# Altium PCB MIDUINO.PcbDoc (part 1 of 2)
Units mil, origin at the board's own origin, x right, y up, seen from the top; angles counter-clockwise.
Board outline 26720 x 2625 mil, 2 copper layers (Top Layer, Bottom Layer); 230 components, 129 nets, 640 pads, 170 vias.
Unrouted connection lines stored in the file: 1.
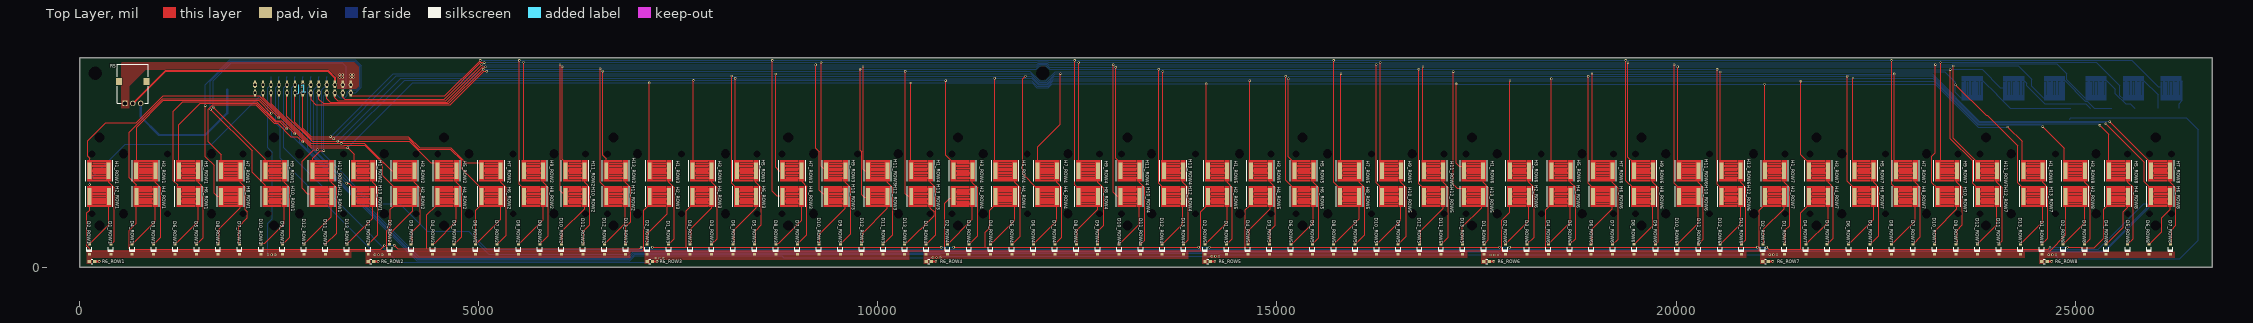
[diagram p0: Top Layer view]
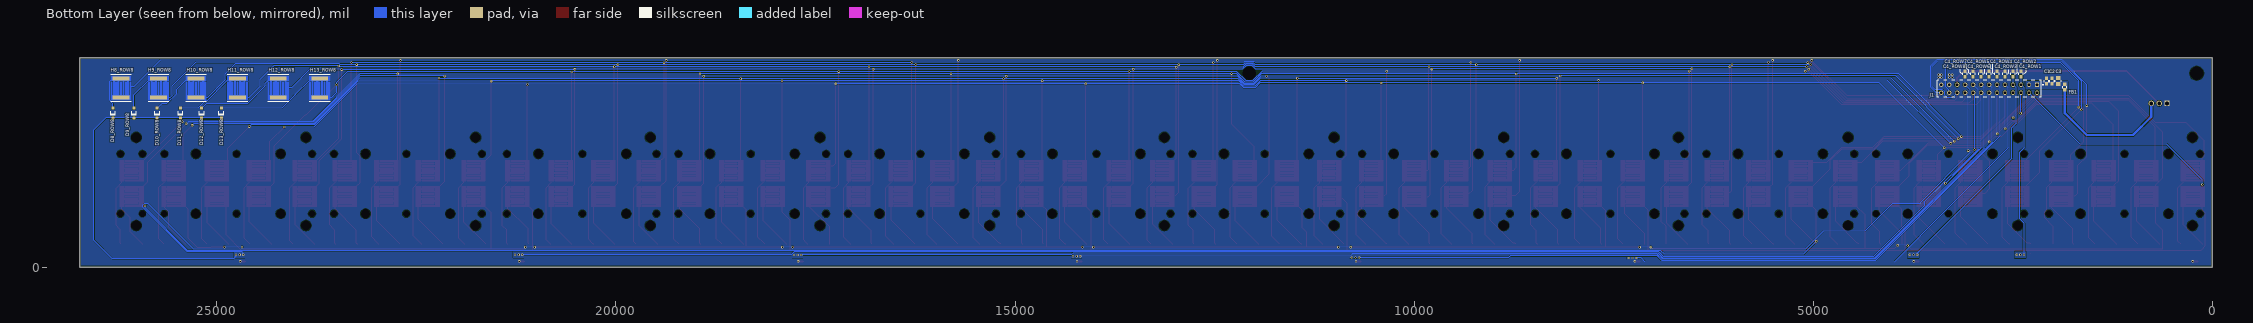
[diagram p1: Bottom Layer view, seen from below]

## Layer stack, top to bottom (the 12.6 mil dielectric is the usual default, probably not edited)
Top Solder: solder mask 0.4, Solder Resist, Dk 3.5
Top Layer: signal copper 1.4
Dielectric 1: dielectric 12.6, FR-4, Dk 4.8
Bottom Layer: signal copper 1.4
Bottom Solder: solder mask 0.4, Solder Resist, Dk 3.5

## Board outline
0,0 0,2625 26720,2625 26720,0

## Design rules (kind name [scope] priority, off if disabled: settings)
AcuteAngle [All] p1: minimum=6.00000000000000E+0001 checktracksonly=FALSE
BoardOutlineClearance [All] p1: gap=20 ignorepadtopadclearanceinfootprint=FALSE
Clearance Clearance_1 [InNamedPolygon('GPS_GND') vs HasFootprint('0603CS')] p1: gap=10 ignorepadtopadclearanceinfootprint=FALSE
Clearance [All] p2: gap=6 ignorepadtopadclearanceinfootprint=FALSE except(0: Arc-Hole Track-Hole SMDPad-Hole THPad-Hole Via-Hole Fill-Hole Poly-Hole Region-Hole Text-Hole; 8: Arc-Poly Track-Poly SMDPad-Poly THPad-Poly Via-Poly Fill-Poly Poly-Poly Poly-Region Poly-Text)
ComponentClearance ComponentClearance_TestPad [HasFootprint('TEST-SMT')] p1: gap=5 collisioncheckmode=3 verticalgap=10 showdistances=FALSE
ComponentClearance [All] p2: gap=10 collisioncheckmode=3 verticalgap=10 showdistances=FALSE
DiffPairsRouting DiffPairsRoutingDBGUSB [InDifferentialPair('USB_DBG')] p1: maxlimit=60 minlimit=10 mostfreqgap=10 toplayer_minwidth=6 toplayer_maxwidth=30 toplayer_prefwidth=10 bottomlayer_minwidth=6 bottomlayer_maxwidth=30 bottomlayer_prefwidth=10 maxuncoupledlength=500
DiffPairsRouting DiffPairsRouting_USBDBG [InDifferentialPair('USB_DBG')] p2: maxlimit=60 minlimit=10 mostfreqgap=10 toplayer_minwidth=6 toplayer_maxwidth=30 toplayer_prefwidth=10 bottomlayer_minwidth=6 bottomlayer_maxwidth=30 bottomlayer_prefwidth=10 maxuncoupledlength=500
DiffPairsRouting DiffPairsRoutingUSB [InDifferentialPair('USB')] p3: maxlimit=60 minlimit=10 mostfreqgap=10 toplayer_minwidth=6 toplayer_maxwidth=30 toplayer_prefwidth=10 bottomlayer_minwidth=6 bottomlayer_maxwidth=30 bottomlayer_prefwidth=10 maxuncoupledlength=500
DiffPairsRouting DP_CAN [InNetClass('CAN')] p4: maxlimit=60 minlimit=10 mostfreqgap=10 toplayer_minwidth=6 toplayer_maxwidth=30 toplayer_prefwidth=6 bottomlayer_minwidth=6 bottomlayer_maxwidth=30 bottomlayer_prefwidth=6 maxuncoupledlength=500 // 120ohm zdiff
DiffPairsRouting DP_USB [InDifferentialPair('USB')] p5: maxlimit=60 minlimit=10 mostfreqgap=10 toplayer_minwidth=6 toplayer_maxwidth=30 toplayer_prefwidth=10 bottomlayer_minwidth=6 bottomlayer_maxwidth=30 bottomlayer_prefwidth=10 maxuncoupledlength=500 // 120ohm zdiff
DiffPairsRouting DP_CURR [InNetClass('CURR')] p6: maxlimit=60 minlimit=10 mostfreqgap=10 toplayer_minwidth=6 toplayer_maxwidth=12 toplayer_prefwidth=6 bottomlayer_minwidth=6 bottomlayer_maxwidth=12 bottomlayer_prefwidth=6 maxuncoupledlength=500 // 120ohm zdiff
DiffPairsRouting [InDifferentialPairClass('All Differential Pairs')] p7: maxlimit=60 minlimit=12 mostfreqgap=12 toplayer_minwidth=6 toplayer_maxwidth=12 toplayer_prefwidth=8 bottomlayer_minwidth=6 bottomlayer_maxwidth=12 bottomlayer_prefwidth=8 maxuncoupledlength=500
Height [All] p1: minheight=0 maxheight=2000 prefheight=500
HoleSize [All] p1: absolutevalues=TRUE maxlimit=250 minlimit=15 maxpercent=80.000 minpercent=20.000
HoleToHoleClearance [All] p1: gap=15 allowstackedmicrovias=FALSE
MinimumAnnularRing [All] p1: minimumring=6
MinimumSolderMaskSliver [All] p1: minsoldermaskwidth=0
PasteMaskExpansion [All] p1: expansion=1
PlaneClearance [All] p1: clearance=10
PlaneConnect [All] p1: planeconnectstyle=Direct reliefexpansion=10 reliefentries=4 reliefconductorwidth=10 reliefairgap=7
PolygonConnect [All] p1: connectstyle=Direct reliefconductorwidth=10 reliefentries=4 polygonreliefangle="90 Angle" airgapwidth=10
RoutingVias [All] p1: holewidth=15 width=30 viastyle="Through Hole" minholewidth=15 minwidth=27 maxholewidth=30 maxwidth=100
SilkToSilkClearance [All] p1: silktosilkclearance=1
SilkToSolderMaskClearance [IsPad] p1: minsilkscreentomaskgap=1 clearancetoexposedcopper=TRUE
SolderMaskExpansion ViaTent [isVia] p1: expansion=-100 istentingtop=FALSE
SolderMaskExpansion ViaTenting [isVia] p2: expansion=-20 istentingtop=FALSE
SolderMaskExpansion [All] p3: expansion=2.5 istentingtop=FALSE
Width [All] p1: maxlimit=250 minlimit=6 preferedwidth=8
19 further rules are at their usual default settings.

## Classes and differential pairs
channel class Row: ROW1 ROW2 ROW3 ROW4 ROW5 ROW6 ROW7 ROW8
component class ROW8: C4_ROW8 D1_ROW8 D2_ROW8 D3_ROW8 D4_ROW8 D5_ROW8 D6_ROW8 D7_ROW8 D8_ROW8 D9_ROW8 D10_ROW8 D11_ROW8 D12_ROW8 D13_ROW8 H1_ROW8 H2_ROW8 H3_ROW8 H4_ROW8 H5_ROW8 H6_ROW8 H7_ROW8 H8_ROW8 H9_ROW8 H10_ROW8 H11_ROW8 H12_ROW8 H13_ROW8 R6_ROW8
component class ROW7: C4_ROW7 D1_ROW7 D2_ROW7 D3_ROW7 D4_ROW7 D5_ROW7 D6_ROW7 D7_ROW7 D8_ROW7 D9_ROW7 D10_ROW7 D11_ROW7 D12_ROW7 D13_ROW7 H1_ROW7 H2_ROW7 H3_ROW7 H4_ROW7 H5_ROW7 H6_ROW7 H7_ROW7 H8_ROW7 H9_ROW7 H10_ROW7 H11_ROW7 H12_ROW7 H13_ROW7 R6_ROW7
component class ROW6: C4_ROW6 D1_ROW6 D2_ROW6 D3_ROW6 D4_ROW6 D5_ROW6 D6_ROW6 D7_ROW6 D8_ROW6 D9_ROW6 D10_ROW6 D11_ROW6 D12_ROW6 D13_ROW6 H1_ROW6 H2_ROW6 H3_ROW6 H4_ROW6 H5_ROW6 H6_ROW6 H7_ROW6 H8_ROW6 H9_ROW6 H10_ROW6 H11_ROW6 H12_ROW6 H13_ROW6 R6_ROW6
component class ROW5: C4_ROW5 D1_ROW5 D2_ROW5 D3_ROW5 D4_ROW5 D5_ROW5 D6_ROW5 D7_ROW5 D8_ROW5 D9_ROW5 D10_ROW5 D11_ROW5 D12_ROW5 D13_ROW5 H1_ROW5 H2_ROW5 H3_ROW5 H4_ROW5 H5_ROW5 H6_ROW5 H7_ROW5 H8_ROW5 H9_ROW5 H10_ROW5 H11_ROW5 H12_ROW5 H13_ROW5 R6_ROW5
component class ROW4: C4_ROW4 D1_ROW4 D2_ROW4 D3_ROW4 D4_ROW4 D5_ROW4 D6_ROW4 D7_ROW4 D8_ROW4 D9_ROW4 D10_ROW4 D11_ROW4 D12_ROW4 D13_ROW4 H1_ROW4 H2_ROW4 H3_ROW4 H4_ROW4 H5_ROW4 H6_ROW4 H7_ROW4 H8_ROW4 H9_ROW4 H10_ROW4 H11_ROW4 H12_ROW4 H13_ROW4 R6_ROW4
component class ROW3: C4_ROW3 D1_ROW3 D2_ROW3 D3_ROW3 D4_ROW3 D5_ROW3 D6_ROW3 D7_ROW3 D8_ROW3 D9_ROW3 D10_ROW3 D11_ROW3 D12_ROW3 D13_ROW3 H1_ROW3 H2_ROW3 H3_ROW3 H4_ROW3 H5_ROW3 H6_ROW3 H7_ROW3 H8_ROW3 H9_ROW3 H10_ROW3 H11_ROW3 H12_ROW3 H13_ROW3 R6_ROW3
component class ROW2: C4_ROW2 D1_ROW2 D2_ROW2 D3_ROW2 D4_ROW2 D5_ROW2 D6_ROW2 D7_ROW2 D8_ROW2 D9_ROW2 D10_ROW2 D11_ROW2 D12_ROW2 D13_ROW2 H1_ROW2 H2_ROW2 H3_ROW2 H4_ROW2 H5_ROW2 H6_ROW2 H7_ROW2 H8_ROW2 H9_ROW2 H10_ROW2 H11_ROW2 H12_ROW2 H13_ROW2 R6_ROW2
net class ROW[1..8]: ROW1 ROW2 ROW3 ROW4 ROW5 ROW6 ROW7 ROW8
net class COL[1..13]: COL1 COL2 COL3 COL4 COL5 COL6 COL7 COL8 COL9 COL10 COL11 COL12 COL13
component class ROW1: C4_ROW1 D1_ROW1 D2_ROW1 D3_ROW1 D4_ROW1 D5_ROW1 D6_ROW1 D7_ROW1 D8_ROW1 D9_ROW1 D10_ROW1 D11_ROW1 D12_ROW1 D13_ROW1 H1_ROW1 H2_ROW1 H3_ROW1 H4_ROW1 H5_ROW1 H6_ROW1 H7_ROW1 H8_ROW1 H9_ROW1 H10_ROW1 H11_ROW1 H12_ROW1 H13_ROW1 R6_ROW1
component class MIDUINO: C1 C2 C3 FB1 R5 R15

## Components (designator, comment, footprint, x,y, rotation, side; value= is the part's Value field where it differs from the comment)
C1 "CAP 0603 0.01UF 25V 10% X7R" 0603_CAP 2080,2330 r270 bottom value=10nF
C2 "CAP 0603 0.1UF 25V 10% X7R" 0603_CAP 2010,2330 r90 bottom value=100nF
C3 "CAP 0805 10UF 16V 20% X7R" 0805_CAP_60H 1930,2331.34 r270 bottom value=10µF
C4_ROW1 "CAP 0603 0.1UF 25V 10% X7R" 0603_CAP 2400,2420 r270 bottom value=100nF (schematic designator C4)
C4_ROW2 "CAP 0603 0.1UF 25V 10% X7R" 0603_CAP 2500,2420 r270 bottom value=100nF (schematic designator C4)
C4_ROW3 "CAP 0603 0.1UF 25V 10% X7R" 0603_CAP 2600,2420 r270 bottom value=100nF (schematic designator C4)
C4_ROW4 "CAP 0603 0.1UF 25V 10% X7R" 0603_CAP 2700,2420 r270 bottom value=100nF (schematic designator C4)
C4_ROW5 "CAP 0603 0.1UF 25V 10% X7R" 0603_CAP 2800,2420 r270 bottom value=100nF (schematic designator C4)
C4_ROW6 "CAP 0603 0.1UF 25V 10% X7R" 0603_CAP 2900,2420 r270 bottom value=100nF (schematic designator C4)
C4_ROW7 "CAP 0603 0.1UF 25V 10% X7R" 0603_CAP 3000,2420 r270 bottom value=100nF (schematic designator C4)
C4_ROW8 "CAP 0603 0.1UF 25V 10% X7R" 0603_CAP 3100,2420 r270 bottom value=100nF (schematic designator C4)
D1_ROW1 "1N4148W-7-F" DIOD-SOD123-2_V 390.79,224 r270 top (schematic designator D1)
D1_ROW2 "1N4148W-7-F" DIOD-SOD123-2_V 3616.32,224 r270 top (schematic designator D1)
D1_ROW3 "1N4148W-7-F" DIOD-SOD123-2_V 7379.43,224 r270 top (schematic designator D1)
D1_ROW4 "1N4148W-7-F" DIOD-SOD123-2_V 10604.96,224 r270 top (schematic designator D1)
D1_ROW5 "1N4148W-7-F" DIOD-SOD123-2_V 14368.07,224 r270 top (schematic designator D1)
D1_ROW6 "1N4148W-7-F" DIOD-SOD123-2_V 17593.6,224 r270 top (schematic designator D1)
D1_ROW7 "1N4148W-7-F" DIOD-SOD123-2_V 21356.71,224 r270 top (schematic designator D1)
D1_ROW8 "1N4148W-7-F" DIOD-SOD123-2_V 24582.24,224 r270 top (schematic designator D1)
D2_ROW1 "1N4148W-7-F" DIOD-SOD123-2_V 122,224 r270 top (schematic designator D2)
D2_ROW2 "1N4148W-7-F" DIOD-SOD123-2_V 3885.11,224 r270 top (schematic designator D2)
D2_ROW3 "1N4148W-7-F" DIOD-SOD123-2_V 7110.64,224 r270 top (schematic designator D2)
D2_ROW4 "1N4148W-7-F" DIOD-SOD123-2_V 10873.75,224 r270 top (schematic designator D2)
D2_ROW5 "1N4148W-7-F" DIOD-SOD123-2_V 14099.28,224 r270 top (schematic designator D2)
D2_ROW6 "1N4148W-7-F" DIOD-SOD123-2_V 17862.39,224 r270 top (schematic designator D2)
D2_ROW7 "1N4148W-7-F" DIOD-SOD123-2_V 21087.92,224 r270 top (schematic designator D2)
D2_ROW8 "1N4148W-7-F" DIOD-SOD123-2_V 24851.03,224 r270 top (schematic designator D2)
D3_ROW1 "1N4148W-7-F" DIOD-SOD123-2_V 928.38,224 r270 top (schematic designator D3)
D3_ROW2 "1N4148W-7-F" DIOD-SOD123-2_V 4153.91,224 r270 top (schematic designator D3)
D3_ROW3 "1N4148W-7-F" DIOD-SOD123-2_V 7917.02,224 r270 top (schematic designator D3)
D3_ROW4 "1N4148W-7-F" DIOD-SOD123-2_V 11142.55,224 r270 top (schematic designator D3)
D3_ROW5 "1N4148W-7-F" DIOD-SOD123-2_V 14905.66,224 r270 top (schematic designator D3)
D3_ROW6 "1N4148W-7-F" DIOD-SOD123-2_V 18131.18,224 r270 top (schematic designator D3)
D3_ROW7 "1N4148W-7-F" DIOD-SOD123-2_V 21894.3,224 r270 top (schematic designator D3)
D3_ROW8 "1N4148W-7-F" DIOD-SOD123-2_V 25119.82,224 r270 top (schematic designator D3)
D4_ROW1 "1N4148W-7-F" DIOD-SOD123-2_V 659.59,224 r270 top (schematic designator D4)
D4_ROW2 "1N4148W-7-F" DIOD-SOD123-2_V 4422.7,224 r270 top (schematic designator D4)
D4_ROW3 "1N4148W-7-F" DIOD-SOD123-2_V 7648.23,224 r270 top (schematic designator D4)
D4_ROW4 "1N4148W-7-F" DIOD-SOD123-2_V 11411.34,224 r270 top (schematic designator D4)
D4_ROW5 "1N4148W-7-F" DIOD-SOD123-2_V 14636.87,224 r270 top (schematic designator D4)
D4_ROW6 "1N4148W-7-F" DIOD-SOD123-2_V 18399.98,224 r270 top (schematic designator D4)
D4_ROW7 "1N4148W-7-F" DIOD-SOD123-2_V 21625.5,224 r270 top (schematic designator D4)
D4_ROW8 "1N4148W-7-F" DIOD-SOD123-2_V 25388.62,224 r270 top (schematic designator D4)
D5_ROW1 "1N4148W-7-F" DIOD-SOD123-2_V 1465.97,224 r270 top (schematic designator D5)
D5_ROW2 "1N4148W-7-F" DIOD-SOD123-2_V 4691.49,224 r270 top (schematic designator D5)
D5_ROW3 "1N4148W-7-F" DIOD-SOD123-2_V 8454.61,224 r270 top (schematic designator D5)
D5_ROW4 "1N4148W-7-F" DIOD-SOD123-2_V 11680.13,224 r270 top (schematic designator D5)
D5_ROW5 "1N4148W-7-F" DIOD-SOD123-2_V 15443.25,224 r270 top (schematic designator D5)
D5_ROW6 "1N4148W-7-F" DIOD-SOD123-2_V 18668.77,224 r270 top (schematic designator D5)
D5_ROW7 "1N4148W-7-F" DIOD-SOD123-2_V 22431.89,224 r270 top (schematic designator D5)
D5_ROW8 "1N4148W-7-F" DIOD-SOD123-2_V 25657.41,224 r270 top (schematic designator D5)
D6_ROW1 "1N4148W-7-F" DIOD-SOD123-2_V 1197.18,224 r270 top (schematic designator D6)
D6_ROW2 "1N4148W-7-F" DIOD-SOD123-2_V 4960.29,224 r270 top (schematic designator D6)
D6_ROW3 "1N4148W-7-F" DIOD-SOD123-2_V 8185.81,224 r270 top (schematic designator D6)
D6_ROW4 "1N4148W-7-F" DIOD-SOD123-2_V 11948.93,224 r270 top (schematic designator D6)
D6_ROW5 "1N4148W-7-F" DIOD-SOD123-2_V 15174.45,224 r270 top (schematic designator D6)
D6_ROW6 "1N4148W-7-F" DIOD-SOD123-2_V 18937.57,224 r270 top (schematic designator D6)
D6_ROW7 "1N4148W-7-F" DIOD-SOD123-2_V 22163.09,224 r270 top (schematic designator D6)
D6_ROW8 "1N4148W-7-F" DIOD-SOD123-2_V 25926.2,224 r270 top (schematic designator D6)
D7_ROW1 "1N4148W-7-F" DIOD-SOD123-2_V 2003.56,224 r270 top (schematic designator D7)
D7_ROW2 "1N4148W-7-F" DIOD-SOD123-2_V 5229.08,224 r270 top (schematic designator D7)
D7_ROW3 "1N4148W-7-F" DIOD-SOD123-2_V 8992.2,224 r270 top (schematic designator D7)
D7_ROW4 "1N4148W-7-F" DIOD-SOD123-2_V 12217.72,224 r270 top (schematic designator D7)
D7_ROW5 "1N4148W-7-F" DIOD-SOD123-2_V 15980.83,224 r270 top (schematic designator D7)
D7_ROW6 "1N4148W-7-F" DIOD-SOD123-2_V 19206.36,224 r270 top (schematic designator D7)
D7_ROW7 "1N4148W-7-F" DIOD-SOD123-2_V 22969.47,224 r270 top (schematic designator D7)
D7_ROW8 "1N4148W-7-F" DIOD-SOD123-2_V 26195,224 r270 top (schematic designator D7)
D8_ROW1 "1N4148W-7-F" DIOD-SOD123-2_V 1734.76,224 r270 top (schematic designator D8)
D8_ROW2 "1N4148W-7-F" DIOD-SOD123-2_V 5497.88,224 r270 top (schematic designator D8)
D8_ROW3 "1N4148W-7-F" DIOD-SOD123-2_V 8723.4,224 r270 top (schematic designator D8)
D8_ROW4 "1N4148W-7-F" DIOD-SOD123-2_V 12486.51,224 r270 top (schematic designator D8)
D8_ROW5 "1N4148W-7-F" DIOD-SOD123-2_V 15712.04,224 r270 top (schematic designator D8)
D8_ROW6 "1N4148W-7-F" DIOD-SOD123-2_V 19475.15,224 r270 top (schematic designator D8)
D8_ROW7 "1N4148W-7-F" DIOD-SOD123-2_V 22700.68,224 r270 top (schematic designator D8)
D8_ROW8 "1N4148W-7-F" DIOD-SOD123-2_V 26301.69,1930.32 r270 bottom (schematic designator D8)
D9_ROW1 "1N4148W-7-F" DIOD-SOD123-2_V 2541.14,224 r270 top (schematic designator D9)
D9_ROW2 "1N4148W-7-F" DIOD-SOD123-2_V 5766.67,224 r270 top (schematic designator D9)
D9_ROW3 "1N4148W-7-F" DIOD-SOD123-2_V 9529.78,224 r270 top (schematic designator D9)
D9_ROW4 "1N4148W-7-F" DIOD-SOD123-2_V 12755.31,224 r270 top (schematic designator D9)
D9_ROW5 "1N4148W-7-F" DIOD-SOD123-2_V 16518.42,224 r270 top (schematic designator D9)
D9_ROW6 "1N4148W-7-F" DIOD-SOD123-2_V 19743.95,224 r270 top (schematic designator D9)
D9_ROW7 "1N4148W-7-F" DIOD-SOD123-2_V 23507.06,224 r270 top (schematic designator D9)
D9_ROW8 "1N4148W-7-F" DIOD-SOD123-2_V 26039,1930.32 r270 bottom (schematic designator D9)
D10_ROW1 "1N4148W-7-F" DIOD-SOD123-2_V 2272.35,224 r270 top (schematic designator D10)
D10_ROW2 "1N4148W-7-F" DIOD-SOD123-2_V 6035.46,224 r270 top (schematic designator D10)
D10_ROW3 "1N4148W-7-F" DIOD-SOD123-2_V 9260.99,224 r270 top (schematic designator D10)
D10_ROW4 "1N4148W-7-F" DIOD-SOD123-2_V 13024.1,224 r270 top (schematic designator D10)
D10_ROW5 "1N4148W-7-F" DIOD-SOD123-2_V 16249.63,224 r270 top (schematic designator D10)
D10_ROW6 "1N4148W-7-F" DIOD-SOD123-2_V 20012.74,224 r270 top (schematic designator D10)
D10_ROW7 "1N4148W-7-F" DIOD-SOD123-2_V 23238.27,224 r270 top (schematic designator D10)
D10_ROW8 "1N4148W-7-F" DIOD-SOD123-2_V 25748,1930.32 r270 bottom (schematic designator D10)
D11_ROW1 "1N4148W-7-F" DIOD-SOD123-2_V 3078.73,224 r270 top (schematic designator D11)
D11_ROW2 "1N4148W-7-F" DIOD-SOD123-2_V 6304.26,224 r270 top (schematic designator D11)
D11_ROW3 "1N4148W-7-F" DIOD-SOD123-2_V 10067.37,224 r270 top (schematic designator D11)
D11_ROW4 "1N4148W-7-F" DIOD-SOD123-2_V 13292.9,224 r270 top (schematic designator D11)
D11_ROW5 "1N4148W-7-F" DIOD-SOD123-2_V 17056.01,224 r270 top (schematic designator D11)
D11_ROW6 "1N4148W-7-F" DIOD-SOD123-2_V 20281.53,224 r270 top (schematic designator D11)
D11_ROW7 "1N4148W-7-F" DIOD-SOD123-2_V 24044.65,224 r270 top (schematic designator D11)
D11_ROW8 "1N4148W-7-F" DIOD-SOD123-2_V 25456,1930.32 r270 bottom (schematic designator D11)
D12_ROW1 "1N4148W-7-F" DIOD-SOD123-2_V 2809.94,224 r270 top (schematic designator D12)
D12_ROW2 "1N4148W-7-F" DIOD-SOD123-2_V 6573.05,224 r270 top (schematic designator D12)
D12_ROW3 "1N4148W-7-F" DIOD-SOD123-2_V 9798.58,224 r270 top (schematic designator D12)
D12_ROW4 "1N4148W-7-F" DIOD-SOD123-2_V 13561.69,224 r270 top (schematic designator D12)
D12_ROW5 "1N4148W-7-F" DIOD-SOD123-2_V 16787.22,224 r270 top (schematic designator D12)
D12_ROW6 "1N4148W-7-F" DIOD-SOD123-2_V 20550.33,224 r270 top (schematic designator D12)
D12_ROW7 "1N4148W-7-F" DIOD-SOD123-2_V 23775.85,224 r270 top (schematic designator D12)
D12_ROW8 "1N4148W-7-F" DIOD-SOD123-2_V 25190,1930.32 r270 bottom (schematic designator D12)
D13_ROW1 "1N4148W-7-F" DIOD-SOD123-2_V 3347.53,224 r270 top (schematic designator D13)
D13_ROW2 "1N4148W-7-F" DIOD-SOD123-2_V 6841.85,224 r270 top (schematic designator D13)
D13_ROW3 "1N4148W-7-F" DIOD-SOD123-2_V 10336.16,224 r270 top (schematic designator D13)
D13_ROW4 "1N4148W-7-F" DIOD-SOD123-2_V 13830.48,224 r270 top (schematic designator D13)
D13_ROW5 "1N4148W-7-F" DIOD-SOD123-2_V 17324.8,224 r270 top (schematic designator D13)
D13_ROW6 "1N4148W-7-F" DIOD-SOD123-2_V 20819.12,224 r270 top (schematic designator D13)
D13_ROW7 "1N4148W-7-F" DIOD-SOD123-2_V 24313.44,224 r270 top (schematic designator D13)
D13_ROW8 "1N4148W-7-F" DIOD-SOD123-2_V 24945,1930.32 r270 bottom (schematic designator D13)
FB1 "Ferrite Chip 2500 Ohms" 0603 1850,2255 r90 bottom
H1_ROW1 "KEYPAD" KEYPAD-Footprint-1 75,1337 r0 top locked (schematic designator H1)
H1_ROW2 "KEYPAD" KEYPAD-Footprint-1 3382,1337 r0 top locked (schematic designator H1)
H1_ROW3 "KEYPAD" KEYPAD-Footprint-1 7093,1337 r0 top (schematic designator H1)
H1_ROW4 "KEYPAD" KEYPAD-Footprint-1 10369,1338 r0 top (schematic designator H1)
H1_ROW5 "KEYPAD" KEYPAD-Footprint-1 14085,1337 r0 top (schematic designator H1)
H1_ROW6 "KEYPAD" KEYPAD-Footprint-1 17295,1337 r0 top (schematic designator H1)
H1_ROW7 "KEYPAD" KEYPAD-Footprint-1 21065,1337 r0 top (schematic designator H1)
H1_ROW8 "KEYPAD" KEYPAD-Footprint-1 24304,1337 r0 top (schematic designator H1)
H2_ROW1 "KEYPAD" KEYPAD-Footprint-1 76,1015 r0 top locked (schematic designator H2)
H2_ROW2 "KEYPAD" KEYPAD-Footprint-1 3904,1015 r0 top locked (schematic designator H2)
H2_ROW3 "KEYPAD" KEYPAD-Footprint-1 7093,1015 r0 top (schematic designator H2)
H2_ROW4 "KEYPAD" KEYPAD-Footprint-1 10896,1014 r0 top (schematic designator H2)
H2_ROW5 "KEYPAD" KEYPAD-Footprint-1 14085,1015 r0 top (schematic designator H2)
H2_ROW6 "KEYPAD" KEYPAD-Footprint-1 17868,1015 r0 top (schematic designator H2)
H2_ROW7 "KEYPAD" KEYPAD-Footprint-1 21065,1015 r0 top (schematic designator H2)
H2_ROW8 "KEYPAD" KEYPAD-Footprint-1 24831,1016 r0 top (schematic designator H2)
H3_ROW1 "KEYPAD" KEYPAD-Footprint-1 659,1337 r0 top locked (schematic designator H3)
H3_ROW2 "KEYPAD" KEYPAD-Footprint-1 3904,1337 r0 top locked (schematic designator H3)
H3_ROW3 "KEYPAD" KEYPAD-Footprint-1 7629,1337 r0 top (schematic designator H3)
H3_ROW4 "KEYPAD" KEYPAD-Footprint-1 10896,1336 r0 top (schematic designator H3)
H3_ROW5 "KEYPAD" KEYPAD-Footprint-1 14625,1337 r0 top (schematic designator H3)
H3_ROW6 "KEYPAD" KEYPAD-Footprint-1 17868,1337 r0 top (schematic designator H3)
H3_ROW7 "KEYPAD" KEYPAD-Footprint-1 21615,1337 r0 top (schematic designator H3)
H3_ROW8 "KEYPAD" KEYPAD-Footprint-1 24831,1338 r0 top (schematic designator H3)
H4_ROW1 "KEYPAD" KEYPAD-Footprint-1 660,1015 r0 top locked (schematic designator H4)
H4_ROW2 "KEYPAD" KEYPAD-Footprint-1 4431,1015 r0 top locked (schematic designator H4)
H4_ROW3 "KEYPAD" KEYPAD-Footprint-1 7629,1015 r0 top (schematic designator H4)
H4_ROW4 "KEYPAD" KEYPAD-Footprint-1 11426,1016 r0 top (schematic designator H4)
H4_ROW5 "KEYPAD" KEYPAD-Footprint-1 14625,1015 r0 top (schematic designator H4)
H4_ROW6 "KEYPAD" KEYPAD-Footprint-1 18388,1015 r0 top (schematic designator H4)
H4_ROW7 "KEYPAD" KEYPAD-Footprint-1 21615,1015 r0 top (schematic designator H4)
H4_ROW8 "KEYPAD" KEYPAD-Footprint-1 25372,1016 r0 top (schematic designator H4)
H5_ROW1 "KEYPAD" KEYPAD-Footprint-1 1194,1337 r0 top locked (schematic designator H5)
H5_ROW2 "KEYPAD" KEYPAD-Footprint-1 4431,1337 r0 top locked (schematic designator H5)
H5_ROW3 "KEYPAD" KEYPAD-Footprint-1 8184,1337 r0 top (schematic designator H5)
H5_ROW4 "KEYPAD" KEYPAD-Footprint-1 11426,1338 r0 top (schematic designator H5)
H5_ROW5 "KEYPAD" KEYPAD-Footprint-1 15168,1337 r0 top (schematic designator H5)
H5_ROW6 "KEYPAD" KEYPAD-Footprint-1 18388,1337 r0 top (schematic designator H5)
H5_ROW7 "KEYPAD" KEYPAD-Footprint-1 22186,1337 r0 top (schematic designator H5)
H5_ROW8 "KEYPAD" KEYPAD-Footprint-1 25372,1338 r0 top (schematic designator H5)
H6_ROW1 "KEYPAD" KEYPAD-Footprint-1 1195,1015 r0 top locked (schematic designator H6)
H6_ROW2 "KEYPAD" KEYPAD-Footprint-1 4986,1015 r0 top locked (schematic designator H6)
H6_ROW3 "KEYPAD" KEYPAD-Footprint-1 8184,1015 r0 top (schematic designator H6)
H6_ROW4 "KEYPAD" KEYPAD-Footprint-1 11953,1015 r0 top (schematic designator H6)
H6_ROW5 "KEYPAD" KEYPAD-Footprint-1 15168,1015 r0 top (schematic designator H6)
H6_ROW6 "KEYPAD" KEYPAD-Footprint-1 18912,1016 r0 top (schematic designator H6)
H6_ROW7 "KEYPAD" KEYPAD-Footprint-1 22186,1015 r0 top (schematic designator H6)
H6_ROW8 "KEYPAD" KEYPAD-Footprint-1 25899,1015 r0 top (schematic designator H6)
H7_ROW1 "KEYPAD" KEYPAD-Footprint-1 1724,1338 r0 top locked (schematic designator H7)
H7_ROW2 "KEYPAD" KEYPAD-Footprint-1 4986,1337 r0 top locked (schematic designator H7)
H7_ROW3 "KEYPAD" KEYPAD-Footprint-1 8756,1338 r0 top (schematic designator H7)
H7_ROW4 "KEYPAD" KEYPAD-Footprint-1 11953,1337 r0 top (schematic designator H7)
H7_ROW5 "KEYPAD" KEYPAD-Footprint-1 15741,1338 r0 top (schematic designator H7)
H7_ROW6 "KEYPAD" KEYPAD-Footprint-1 18912,1338 r0 top (schematic designator H7)
H7_ROW7 "KEYPAD" KEYPAD-Footprint-1 22706,1337 r0 top (schematic designator H7)
H7_ROW8 "KEYPAD" KEYPAD-Footprint-1 25899,1337 r0 top (schematic designator H7)
H8_ROW1 "KEYPAD" KEYPAD-Footprint-1 1724,1016 r0 top locked (schematic designator H8)
H8_ROW2 "KEYPAD" KEYPAD-Footprint-1 5517,1015 r0 top locked (schematic designator H8)
H8_ROW3 "KEYPAD" KEYPAD-Footprint-1 8756,1015 r0 top (schematic designator H8)
H8_ROW4 "KEYPAD" KEYPAD-Footprint-1 12467,1016 r0 top (schematic designator H8)
H8_ROW5 "KEYPAD" KEYPAD-Footprint-1 15741,1016 r0 top (schematic designator H8)
H8_ROW6 "KEYPAD" KEYPAD-Footprint-1 19421,1015 r0 top (schematic designator H8)
H8_ROW7 "KEYPAD" KEYPAD-Footprint-1 22706,1015 r0 top (schematic designator H8)
H8_ROW8 "KEYPAD" KEYPAD-Footprint-1 26331,2072.01 r90 bottom (schematic designator H8)
H9_ROW1 "KEYPAD" KEYPAD-Footprint-1 2277,1337 r0 top locked (schematic designator H9)
H9_ROW2 "KEYPAD" KEYPAD-Footprint-1 5517,1337 r0 top locked (schematic designator H9)
H9_ROW3 "KEYPAD" KEYPAD-Footprint-1 9304,1338 r0 top (schematic designator H9)
H9_ROW4 "KEYPAD" KEYPAD-Footprint-1 12467,1338 r0 top (schematic designator H9)
H9_ROW5 "KEYPAD" KEYPAD-Footprint-1 16264,1338 r0 top (schematic designator H9)
H9_ROW6 "KEYPAD" KEYPAD-Footprint-1 19421,1337 r0 top (schematic designator H9)
H9_ROW7 "KEYPAD" KEYPAD-Footprint-1 23229,1337 r0 top (schematic designator H9)
H9_ROW8 "KEYPAD" KEYPAD-Footprint-1 25861,2072.01 r90 bottom (schematic designator H9)
H10_ROW1 "KEYPAD" KEYPAD-Footprint-1 2277,1015 r0 top locked (schematic designator H10)
H10_ROW2 "KEYPAD" KEYPAD-Footprint-1 6037,1015 r0 top (schematic designator H10)
H10_ROW3 "KEYPAD" KEYPAD-Footprint-1 9304,1015 r0 top (schematic designator H10)
H10_ROW4 "KEYPAD" KEYPAD-Footprint-1 12988,1016 r0 top (schematic designator H10)
H10_ROW5 "KEYPAD" KEYPAD-Footprint-1 16264,1016 r0 top (schematic designator H10)
H10_ROW6 "KEYPAD" KEYPAD-Footprint-1 19990,1015 r0 top (schematic designator H10)
H10_ROW7 "KEYPAD" KEYPAD-Footprint-1 23229,1015 r0 top (schematic designator H10)
H10_ROW8 "KEYPAD" KEYPAD-Footprint-1 25391,2072.01 r90 bottom (schematic designator H10)
H11_ROW1 "KEYPAD" KEYPAD-Footprint-1 2865,1337 r0 top locked (schematic designator H11)
H11_ROW2 "KEYPAD" KEYPAD-Footprint-1 6037,1337 r0 top locked (schematic designator H11)
H11_ROW3 "KEYPAD" KEYPAD-Footprint-1 9830,1338 r0 top (schematic designator H11)
H11_ROW4 "KEYPAD" KEYPAD-Footprint-1 12988,1338 r0 top (schematic designator H11)
H11_ROW5 "KEYPAD" KEYPAD-Footprint-1 16792,1337 r0 top (schematic designator H11)
H11_ROW6 "KEYPAD" KEYPAD-Footprint-1 19990,1337 r0 top (schematic designator H11)
H11_ROW7 "KEYPAD" KEYPAD-Footprint-1 23731,1337 r0 top (schematic designator H11)
H11_ROW8 "KEYPAD" KEYPAD-Footprint-1 24872,2072.01 r90 bottom (schematic designator H11)
H12_ROW1 "KEYPAD" KEYPAD-Footprint-1 2865,1015 r0 top locked (schematic designator H12)
H12_ROW2 "KEYPAD" KEYPAD-Footprint-1 6548,1015 r0 top locked (schematic designator H12)
H12_ROW3 "KEYPAD" KEYPAD-Footprint-1 9830,1015 r0 top (schematic designator H12)
H12_ROW4 "KEYPAD" KEYPAD-Footprint-1 13533,1015 r0 top (schematic designator H12)
H12_ROW5 "KEYPAD" KEYPAD-Footprint-1 16792,1015 r0 top (schematic designator H12)
H12_ROW6 "KEYPAD" KEYPAD-Footprint-1 20520,1016 r0 top (schematic designator H12)
H12_ROW7 "KEYPAD" KEYPAD-Footprint-1 23731,1015 r0 top (schematic designator H12)
H12_ROW8 "KEYPAD" KEYPAD-Footprint-1 24362,2072.01 r90 bottom (schematic designator H12)
H13_ROW1 "KEYPAD" KEYPAD-Footprint-1 3382,1015 r0 top locked (schematic designator H13)
H13_ROW2 "KEYPAD" KEYPAD-Footprint-1 6548,1337 r0 top locked (schematic designator H13)
H13_ROW3 "KEYPAD" KEYPAD-Footprint-1 10369,1015 r0 top (schematic designator H13)
H13_ROW4 "KEYPAD" KEYPAD-Footprint-1 13533,1337 r0 top (schematic designator H13)
H13_ROW5 "KEYPAD" KEYPAD-Footprint-1 17295,1015 r0 top (schematic designator H13)
H13_ROW6 "KEYPAD" KEYPAD-Footprint-1 20520,1338 r0 top (schematic designator H13)
H13_ROW7 "KEYPAD" KEYPAD-Footprint-1 24304,1015 r0 top (schematic designator H13)
H13_ROW8 "KEYPAD" KEYPAD-Footprint-1 23842,2072.01 r90 bottom (schematic designator H13)
J1 "6-146256-3" FP-6-146256-3-MFG 2798,2235 r0 bottom
R5 "P090S-14T20BR10K" RES-POT-3 667,2327 r0 top
R6_ROW1 "10K Ohms" 0603_RES 155,72 r180 top value=10K (schematic designator R6)
R6_ROW2 "10K Ohms" 0603_RES 3650,72 r180 top value=10K (schematic designator R6)
R6_ROW3 "10K Ohms" 0603_RES 7143.64,72 r180 top value=10K (schematic designator R6)
R6_ROW4 "10K Ohms" 0603_RES 10637.96,72 r180 top value=10K (schematic designator R6)
R6_ROW5 "10K Ohms" 0603_RES 14132.28,72 r180 top value=10K (schematic designator R6)
R6_ROW6 "10K Ohms" 0603_RES 17626.6,72 r180 top value=10K (schematic designator R6)
R6_ROW7 "10K Ohms" 0603_RES 21120.92,72 r180 top value=10K (schematic designator R6)
R6_ROW8 "10K Ohms" 0603_RES 24615.24,72 r180 top value=10K (schematic designator R6)

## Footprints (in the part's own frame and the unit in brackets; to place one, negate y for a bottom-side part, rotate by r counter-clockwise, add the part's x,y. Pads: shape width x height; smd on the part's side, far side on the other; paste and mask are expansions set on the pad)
0603 [mil] "Body 1.6 x 0.8 mm (LxW typ)"
  rect 43x39 smd: 1(-33.5,0) 2(33.5,0)
  silkscreen extent -12,-27 12,27, body extent -34,-19 34,19, height 38
0603_CAP [mm]
  rect 1.1x1 smd: 1(-0.85,0) 2(0.85,0)
  silkscreen extent -0.3,-0.7 0.3,0.7, body extent -0.8,-0.43 0.8,0.43, height 0.95
0603_RES [mil]
  rect 43x39 smd: 1(-33.46,0) 2(33.46,0)
  silkscreen extent -12,-28 12,28, body extent -32,-19 32,19, height 34
0805_CAP_60H [mm]
  rect 1.3x1.5 smd: 1(-0.95,0) 2(0.95,0)
  silkscreen extent -0.3,-0.97 0.3,0.97, body extent -1,-0.65 1,0.66, height 1.52
DIOD-SOD123-2_V [mm] "SOD123, 2-Leads, Body 2.7x1.55mm, Height 1.45mm"
  rect 0.9x0.95 smd: 1(-1.575,0) 2(1.575,0)
  silkscreen extent -0.64,-0.83 0.64,0.77, body extent -1.35,-0.77 1.35,0.77, height 1.45
FP-6-146256-3-MFG [mm]
  rect 0.76x2.29 smd far side paste+0 mask+0: 1(-15.24,-1.395) 2(-15.24,1.395) 3(-12.7,-1.395) 4(-12.7,1.395) 5(-10.16,-1.395) 6(-10.16,1.395) 7(-7.62,-1.395) 8(-7.62,1.395) 9(-5.08,-1.395) 10(-5.08,1.395) 11(-2.54,-1.395) 12(-2.54,1.395) 13(0,-1.395) 14(0,1.395) 15(2.54,-1.395) 16(2.54,1.395) 17(5.08,-1.395) 18(5.08,1.395) 19(7.62,-1.395) 20(7.62,1.395) 21(10.16,-1.395) 22(10.16,1.395) 23(12.7,-1.395) 24(12.7,1.395) 25(15.24,-1.395) 26(15.24,1.395)
  rect 1.39x1.39 hole 0.89 paste-1000 mask+0: 1(-15.24,-1.27)
  silkscreen extent -17.28,-2.7 16.56,2.7, body extent -16.31,-2.44 16.31,2.44, height 8.69
KEYPAD-Footprint-1 [mil]
  rect 50x210 smd paste+0 mask+0: 1(50,-130)
  rect 50x210 smd mask+0: 2(290,-130)
  Top Layer region: 70,-240 250,-240 250,-260 70,-260
  Top Layer region: 90,-210 270,-210 270,-230 90,-230
  Top Layer region: 90,-150 270,-150 270,-170 90,-170
  Top Layer region: 70,-180 250,-180 250,-200 70,-200
  Top Layer region: 70,-120 250,-120 250,-140 70,-140
  Top Layer region: 90,-90 270,-90 270,-110 90,-110
  Top Layer region: 70,-60 250,-60 250,-80 70,-80
  Top Layer region: 70,0 250,0 250,-20 70,-20
  Top Layer region: 90,-30 270,-30 270,-50 90,-50
  Top Layer region: 20,0 20,-260 80,-260 80,0
  Top Layer region: 260.06,0 260.07,-260 320,-260 320,0
  silkscreen extent 0,-260 340,0
RES-POT-3 [mm] "POT, 3-Leads, Body 9.8x12.5mm, Pitch 2.5mm"
  rect 1.7x1.7 hole 1.2: 1(-2.5,-7)
  round 1.7 hole 1.2: 2(0,-7) 3(2.5,-7)
  rect 1.9x2.3 smd: MP1(-4.35,0) MP2(4.35,0)
  silkscreen extent -4.9,-7 4.9,5.5, body extent -4.9,-7 4.9,5.5, height 26.8

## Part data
C1: library part "CAP 0603 0.01UF 25V 10% X7R-2", "Capacitor Surface Mount 0603 Footprint 0.01UF 25V 10% Tolerance Ceramic X7R", Capacitor Type=Ceramic, Case/Package=0603, Manufacturer=Various, Tolerance=10%, Voltage=25V
C2 C4_ROW1 C4_ROW2 C4_ROW3 C4_ROW4 C4_ROW5 C4_ROW6 C4_ROW7 C4_ROW8: library part "CAP 0603 0.1UF 25V 10% X7R-4", "Capacitor Surface Mount 0603 Footprint 0.1UF 25V 10% Tolerance Ceramic X7R", Capacitor Type=Ceramic, Case/Package=0603, Manufacturer=Various, Tolerance=10%, Voltage=25V
C3: library part "CAP 0805 10UF 16V 20% X7R-2", "Capacitor Surface Mount 0805 Footprint 10UF 16V 20% Tolerance Ceramic X7R", Capacitor Type=Ceramic, Case/Package=0805, Manufacturer=Various, Tolerance=20%, Voltage=16V
D1_ROW1 D1_ROW2 D1_ROW3 D1_ROW4 D1_ROW5 D1_ROW6 D1_ROW7 D1_ROW8 D2_ROW1 D2_ROW2 D2_ROW3 D2_ROW4 D2_ROW5 D2_ROW6 D2_ROW7 D2_ROW8 D3_ROW1 D3_ROW2 D3_ROW3 D3_ROW4 D3_ROW5 D3_ROW6 D3_ROW7 D3_ROW8 D4_ROW1 D4_ROW2 D4_ROW3 D4_ROW4 D4_ROW5 D4_ROW6 D4_ROW7 D4_ROW8 D5_ROW1 D5_ROW2 D5_ROW3 D5_ROW4 D5_ROW5 D5_ROW6 D5_ROW7 D5_ROW8 D6_ROW1 D6_ROW2 D6_ROW3 D6_ROW4 D6_ROW5 D6_ROW6 D6_ROW7 D6_ROW8 D7_ROW1 D7_ROW2 D7_ROW3 D7_ROW4 D7_ROW5 D7_ROW6 D7_ROW7 D7_ROW8 D8_ROW1 D8_ROW2 D8_ROW3 D8_ROW4 D8_ROW5 D8_ROW6 D8_ROW7 D8_ROW8 D9_ROW1 D9_ROW2 D9_ROW3 D9_ROW4 D9_ROW5 D9_ROW6 D9_ROW7 D9_ROW8 D10_ROW1 D10_ROW2 D10_ROW3 D10_ROW4 D10_ROW5 D10_ROW6 D10_ROW7 D10_ROW8 D11_ROW1 D11_ROW2 D11_ROW3 D11_ROW4 D11_ROW5 D11_ROW6 D11_ROW7 D11_ROW8 D12_ROW1 D12_ROW2 D12_ROW3 D12_ROW4 D12_ROW5 D12_ROW6 D12_ROW7 D12_ROW8 D13_ROW1 D13_ROW2 D13_ROW3 D13_ROW4 D13_ROW5 D13_ROW6 D13_ROW7 D13_ROW8: library part CMP-2000-04932-2, "Fast Switching Diode, 100 V, 0.15 A, -65 to 150 degC, 2-Pin?SOD123, RoHS, Tape and Reel", If - Forward Current=0.15A, Ir - Reverse Current=1uA, Manufacturer=DiodesIncorporated, Max Surge Current=2A, Maximum Operating Temperature=+150C, Minimum Operating Temperature=-65C, Operating Temperature Range=-65Cto+150C, Package / Case=SOD-123, Package Reference=SOD123-2, Peak Reverse Voltage=100V, Vf - Forward Voltage=1.25V
FB1: library part MMZ1608A252B-2, "Ferrite Chip 200 mA 2500 Ohms Differential Mode - Single 0603 Footprint", Current (mA)=200, DC Resistance (ohms)=0.8, Frequency="100 MHz", Impedance at Freq (ohms)=2500, Manufacturer=TDK, Manufacturer P/N=MMZ1608A252B, Operating Temperature Range="-55 to +125 °C", PCB Package=0603
H1_ROW1 H1_ROW2 H1_ROW3 H1_ROW4 H1_ROW5 H1_ROW6 H1_ROW7 H1_ROW8 H2_ROW1 H2_ROW2 H2_ROW3 H2_ROW4 H2_ROW5 H2_ROW6 H2_ROW7 H2_ROW8 H3_ROW1 H3_ROW2 H3_ROW3 H3_ROW4 H3_ROW5 H3_ROW6 H3_ROW7 H3_ROW8 H4_ROW1 H4_ROW2 H4_ROW3 H4_ROW4 H4_ROW5 H4_ROW6 H4_ROW7 H4_ROW8 H5_ROW1 H5_ROW2 H5_ROW3 H5_ROW4 H5_ROW5 H5_ROW6 H5_ROW7 H5_ROW8 H6_ROW1 H6_ROW2 H6_ROW3 H6_ROW4 H6_ROW5 H6_ROW6 H6_ROW7 H6_ROW8 H7_ROW1 H7_ROW2 H7_ROW3 H7_ROW4 H7_ROW5 H7_ROW6 H7_ROW7 H7_ROW8 H8_ROW1 H8_ROW2 H8_ROW3 H8_ROW4 H8_ROW5 H8_ROW6 H8_ROW7 H8_ROW8 H9_ROW1 H9_ROW2 H9_ROW3 H9_ROW4 H9_ROW5 H9_ROW6 H9_ROW7 H9_ROW8 H10_ROW1 H10_ROW2 H10_ROW3 H10_ROW4 H10_ROW5 H10_ROW6 H10_ROW7 H10_ROW8 H11_ROW1 H11_ROW2 H11_ROW3 H11_ROW4 H11_ROW5 H11_ROW6 H11_ROW7 H11_ROW8 H12_ROW1 H12_ROW2 H12_ROW3 H12_ROW4 H12_ROW5 H12_ROW6 H12_ROW7 H12_ROW8 H13_ROW1 H13_ROW2 H13_ROW3 H13_ROW4 H13_ROW5 H13_ROW6 H13_ROW7 H13_ROW8: library part CMP-00322-7, "Piano keypad"
J1: library part CMP-03369-000069-1, "CONN HEADER VERT 26POS 2.54MM", Current Rating=3A, Manufacturer="TE Connectivity", Temperature="-65°C to +105°C", Temperature Range High=+105°C, Temperature Range Low=-65°C, Voltage Rating=30V
R5: library part CMP-2000-06871-1, "9 mm Rotary Potentiometer, Insulated Shaft, Conductive Plastic Element, 10 KOhm, -20 to 70 degC, 3-Pin THD, RoHS, Tray", Manufacturer="BI Technologies", Package Description="POT, 3-Leads, Body 9.8 x 12.5 mm, Pitch 2.5 mm", Package Reference=POT-3, Power (Watts)=0.03W,1/32W, Power Rating=0.03W, Resistance (Ohms)=10k, Resistive Material=ConductivePlastic, Standard Package=1, Temperature Coefficient=-, Tolerance=±20%
R6_ROW1 R6_ROW2 R6_ROW3 R6_ROW4 R6_ROW5 R6_ROW6 R6_ROW7 R6_ROW8: library part "RES 0603 10K 10%-1", "Resistor Surface Mount, 10K Ohms, 0603 Footprint, 10% Tolerance 0.1W", Manufacturer=Various, PCB Package=0603, Power_Rating=0.1W, Tolerance=10%

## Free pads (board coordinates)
  round 60 hole 170: 2(197,2428) 2(12067,2428)
  round 60 hole 126: 2(250,521) 2(250,1625) 2(2438,521) 2(2438,1625) 2(4564,521) 2(4564,1625) 2(6690,521) 2(6690,1625) 2(8878,521) 2(8878,1625) 2(11004,521) 2(11004,1625) 2(13130,521) 2(13130,1625) 2(15318,521) 2(15318,1625) 2(17444,521) 2(17444,1625) 2(19570,521) 2(19570,1625) 2(21758,521) 2(21758,1625) 2(23884,521) 2(23884,1625) 2(26010,521) 2(26010,1625)
  round 60 hole 86.6: 3(155,1419) 3(156,669) 3(1101,1419) 3(1102,669) 3(2047,1419) 3(2048,669) 3(2360,1419) 3(2361,669) 3(3306,1419) 3(3307,669) 3(4212,1419) 3(4213,669) 3(4487,1419) 3(4488,669) 3(5432,1419) 3(5433,669) 3(6338,1419) 3(6339,669) 3(6613,1419) 3(6614,669) 3(7541,1419) 3(7542,669) 3(8487,1419) 3(8488,669) 3(8800,1419) 3(8801,669) 3(9746,1419) 3(9747,669) 3(10652,1419) 3(10653,669) 3(10927,1419) 3(10928,669) 3(11872,1419) 3(11873,669) 3(12778,1419) 3(12779,669) 3(13053,1419) 3(13054,669) 3(13981,1419) 3(13982,669) 3(14927,1419) 3(14928,669) 3(15240,1419) 3(15241,669) 3(16186,1419) 3(16187,669) 3(17092,1419) 3(17093,669) 3(17367,1419) 3(17368,669) 3(18312,1419) 3(18313,669) 3(19218,1419) 3(19219,669) 3(19493,1419) 3(19494,669) 3(20421,1419) 3(20422,669) 3(21367,1419) 3(21368,669) 3(21680,1419) 3(21681,669) 3(22626,1419) 3(22627,669) 3(23532,1419) 3(23533,669) 3(23807,1419) 3(23808,669) 3(24752,1419) 3(24753,669) 3(25658,1419) 3(25659,669) 3(25933,1419) 3(25934,669) 3(26208,1419) 3(26209,669)
  round 60 hole 116: 4(550,1419) 4(551,669) 4(1652,1419) 4(1653,669) 4(2755,1419) 4(2756,669) 4(3817,1419) 4(3818,669) 4(4880,1419) 4(4881,669) 4(5943,1419) 4(5944,669) 4(6990,1419) 4(6991,669) 4(8092,1419) 4(8093,669) 4(9195,669) 4(9195,1419) 4(10257,1419) 4(10258,669) 4(11321,669) 4(11321,1419) 4(12383,1419) 4(12384,669) 4(13430,1419) 4(13431,669) 4(14532,1419) 4(14533,669) 4(15635,1419) 4(15636,669) 4(16697,1419) 4(16698,669) 4(17760,1419) 4(17762,669) 4(18823,1419) 4(18824,669) 4(19870,1419) 4(19871,669) 4(20972,1419) 4(20973,669) 4(22075,1419) 4(22076,669) 4(23137,1419) 4(23138,669) 4(24201,669) 4(24201,1419) 4(25263,1419) 4(25264,669)

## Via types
v1: diameter 30, hole 15, Top Layer to Bottom Layer, 145 vias
v2: diameter 54.72, hole 35.04, Top Layer to Bottom Layer, 25 vias

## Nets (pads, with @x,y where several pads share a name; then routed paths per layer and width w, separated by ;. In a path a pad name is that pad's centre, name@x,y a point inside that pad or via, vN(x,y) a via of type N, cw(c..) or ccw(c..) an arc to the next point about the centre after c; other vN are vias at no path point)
5V: FB1.1 R5.3 | length 1751.9
  Bottom Layer w30: R5.3@765.43,2051.41 765.43,1884.57 995,1655 1575,1655 1850,1930 FB1.1@1850,2221.5
ANA0: J1.21 R5.2 | length 2821.3
  Top Layer w25: R5.2@667,2051.41 671.51,2051.41 1075.1,2455 3118,2455 3198,2375 J1.21@3198,2289.92 v2(3198,2285)
COL1: H1_ROW1.1 H1_ROW2.1 H1_ROW3.1 H1_ROW4.1 H1_ROW5.1 H1_ROW6.1 H1_ROW7.1 H1_ROW8.1 J1.2 | length 31886.9
  Top Layer w10: H1_ROW1.1@125,1207 125,1362.1 100.7,1386.4 100.7,1580.35 330.35,1810 710,1810 1045,2145 2188.04,2145 2198,2154.96 v2(2198,2185) ; J1.2@2207.96,2160.9 2207.96,2146.76 2222.1,2146.76 2253.25,2146.75 2904,1496 3359,1496 3440,1415 3440,1315 3437,1312 3437,1212 H1_ROW2.1@3432,1207 ; v1(7139,2308) 7139,1211 H1_ROW3.1@7143,1207 ; v1(10414.5,2306.5) 10414.5,1212.5 H1_ROW4.1@10419,1208 ; v1(14115,2295) 14115,1227 H1_ROW5.1@14135,1207 ; v1(17245.09,2294.91) 17245.09,1301.91 17286,1261 H1_ROW6.1@17325,1261 ; v1(21108.77,2291.23) 21108.77,1213.23 H1_ROW7.1@21115,1207 ; v1(24155,1755) 24335,1575 24335,1325
  Bottom Layer w10: v1(3360,1495) 4173,2308 v1(7139,2308) 7139.75,2307.25 10413.75,2307.25 v1@10416,2305 ; v1@10416,2307.25 11932.75,2307.25 11990.77,2249.23 12137.23,2249.23 12183,2295 v1(14115,2295) v1(14115,2295) v1@17245.04,2294.96 ; v1@17246.93,2293.07 21106.93,2293.07 v1(21108.77,2291.23) 23248.77,2291.23 23785,1755 v1(24155,1755)
COL2: H2_ROW1.1 H2_ROW2.1 H2_ROW3.1 H2_ROW4.1 H2_ROW5.1 H2_ROW6.1 H2_ROW7.1 H2_ROW8.1 J1.4 | length 35572.4
  Top Layer w10: H2_ROW1.1@125,841.07 125,714.79 90,679.79 90,265 147.5,207.5 3845,207.5 ; v1(125.51,1035.51) 125.51,885.49 H2_ROW1.1@126,885 ; v2(2298,2185) 2302.63,2180.37 2302.63,2120 2899.63,1523 3317.29,1523 3318,1523.72 3571.28,1523.72 3795,1300 3795,1145 3940.86,999.14 3940.86,898.14 H2_ROW2.1@3954,885 3939,870 3939,769 3895,725 3895,506.75 3845,456.75 3845,207.5 ; H2_ROW3.1@7143,885 7128,870 7128,773 7065,710 7065,207.5 ; H2_ROW4.1@10946,884 10946,880 10926,860 10900,860 10839.3,799.3 10839.3,207.5 ; H2_ROW5.1@14135,885 14120.86,870.86 14120.86,770.86 14045,695 14045,207.5 ; H2_ROW6.1@17918,965 H2_ROW6.1@17918,885 17918,688 17815,585 17815,207.5 ; H2_ROW7.1@21115,885 21100.86,870.86 21100.86,770.86 21045,715 21045,207.5 ; H2_ROW8.1@24881,886 24881,402.46 24686.04,207.5 21045,207.5 ; 3845,207.5 7065,207.5 ; 7065,207.5 10839.3,207.5 ; 10839.3,207.5 14045,207.5 ; 14045,207.5 17815,207.5 ; 17815,207.5 21045,207.5
  Bottom Layer w10: v1(125.51,1035.51) 125.51,1092.09 501.21,1467.79 573.42,1540 1653,1540 v2(2298,2185)
COL3: H3_ROW1.1 H3_ROW2.1 H3_ROW3.1 H3_ROW4.1 H3_ROW5.1 H3_ROW6.1 H3_ROW7.1 H3_ROW8.1 J1.6 | length 33102.1
  Top Layer w10: H3_ROW1.1@709,1207 715,1213 715,1755 1050,2090 2241.77,2090 v1(2402.88,1928.88) ; v2(2398,2185) J1.6@2398,2180.08 2398,2047.25 2895.6,1549.66 v1(3277.64,1549.66) 3277.99,1550 3567.63,1550 3910.63,1207 H3_ROW2.1@3954,1207 ; H3_ROW3.1@7679,1207 7690,1218 7690,2338.86 v1(7690.7,2339.56) ; v1(10850,2337) 10850,1400 10931,1319 10931,1221 H3_ROW4.1@10946,1206 ; v1(14660.08,2334.83) 14660.08,1221.91 H3_ROW5.1@14675,1207 ; H3_ROW6.1@17918,1207 17920,1209 v1(17920,2335) ; v1(21565,2330) 21565,1405 21650,1320 21650,1222 H3_ROW7.1@21665,1207 ; v1(24593.29,1760) 24866,1487.29 24866,1223 H3_ROW8.1@24881,1208
  Bottom Layer w10: v2(2398,2185) 2400.44,2182.56 2400.44,1931.33 v1(2402.88,1928.88) ; v1(3277.64,1549.66) 4070.99,2343 7687.27,2343 v1(7690.7,2339.56) ; v1@7693.71,2338.28 10843.28,2338.28 v1@10850,2345 ; v1(10850,2337) v1@10850,2345 ; v1(24593.29,1760) 24592.87,1760 24571.87,1781 23781.63,1781 23232.63,2330 21570,2330 21565,2335 v1(17920,2335) 17919.92,2334.91 14660.17,2334.91 v1(14660.08,2334.83) 14659.92,2335 12200.37,2335 12133.37,2268 11997,2268 11928,2337 10858,2337 v1@10850,2345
